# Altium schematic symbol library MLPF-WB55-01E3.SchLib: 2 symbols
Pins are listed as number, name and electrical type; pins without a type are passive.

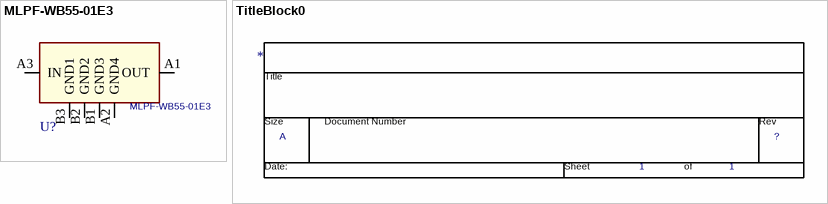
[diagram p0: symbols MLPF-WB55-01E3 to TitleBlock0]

## MLPF-WB55-01E3
designator U?
footprint ST_CSP650x58P2x3_160x100x42
pins: A1 OUT, A2 GND4, A3 IN, B1 GND3, B2 GND2, B3 GND1

## TitleBlock0
designator *  Page Count: 1  Page Size: A  (graphical)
